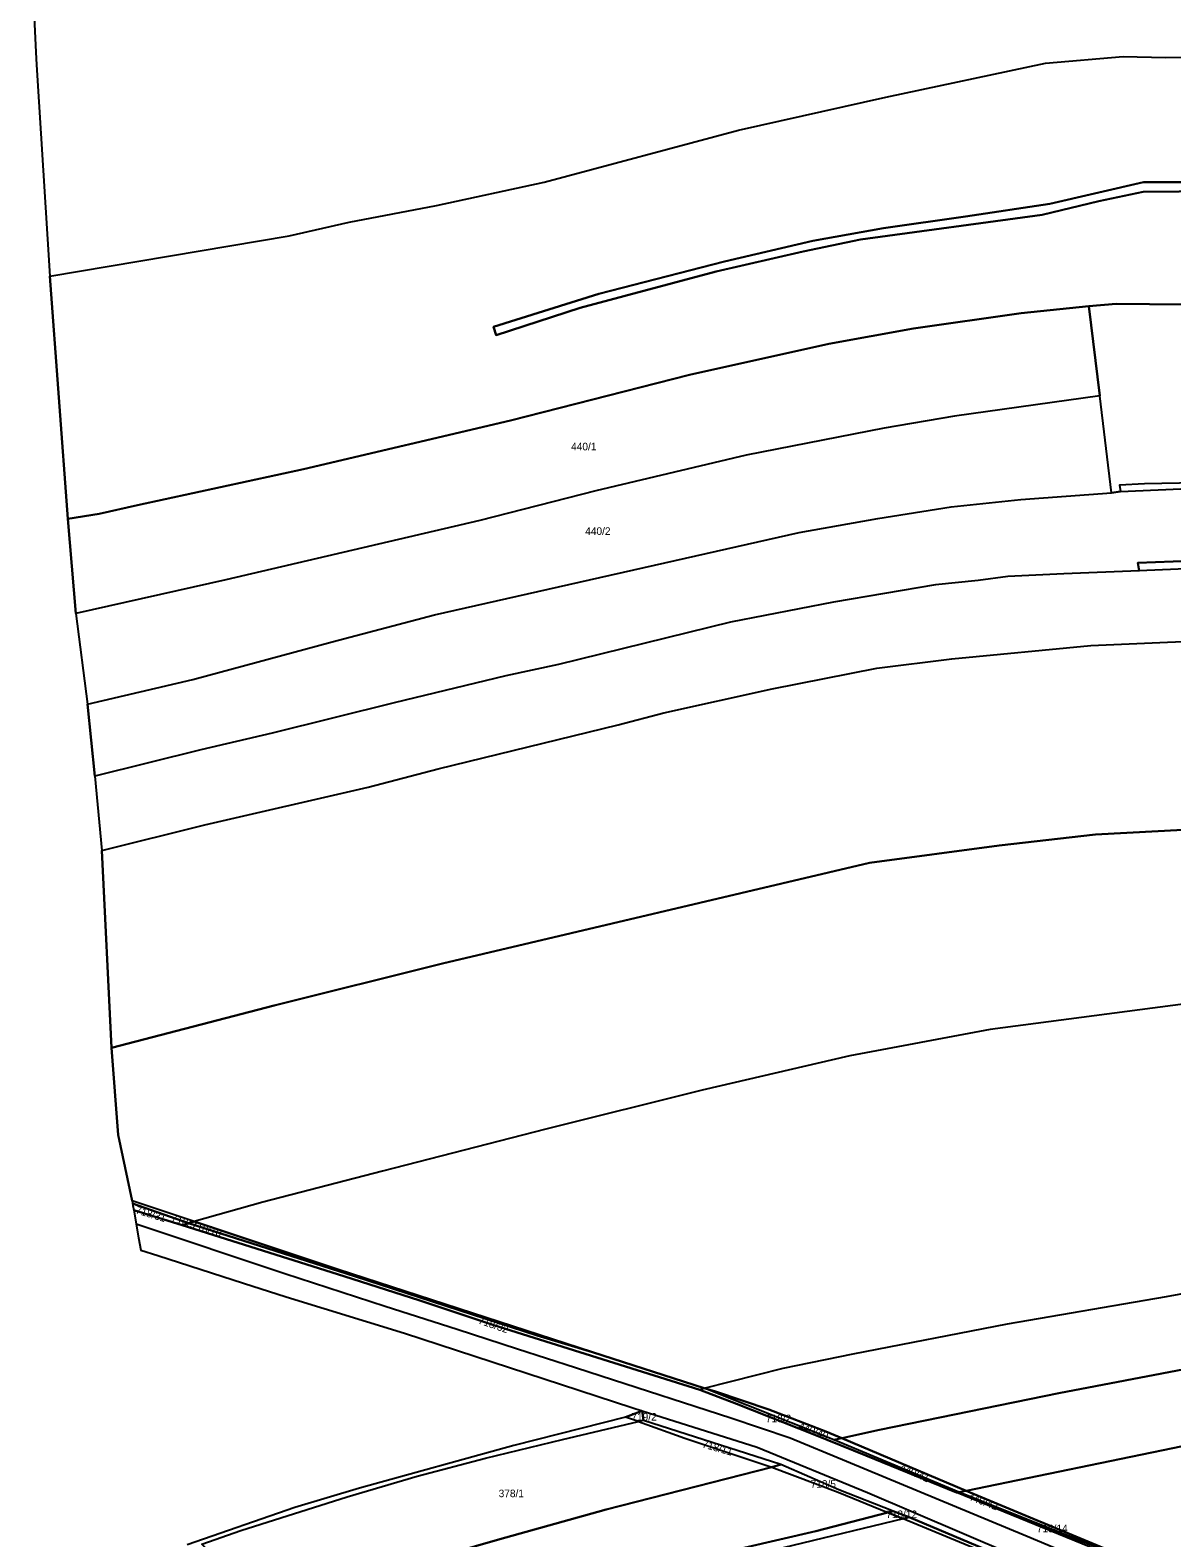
# Model space of a CAD drawing. Extents: x -629983 to -626385, y -1072828 to -1067897.
# Drawn here: x -629139 to -628686, y -1070643 to -1070045 of the extents above; entities that cross this region are included whole.
import ezdxf

# ---------------------------------------------------------------- set-up
doc = ezdxf.new("R2010")
doc.units = 0
for name, color, linetype in [('Parcela nároku', 7, 'Continuous'), ('Parcelní číslo', 7, 'Continuous'), ('Plocha PÚ', 7, 'Continuous'), ('Převzatý obvod_Ostrov', 7, 'Continuous'), ('Silnice ŘSD', 7, 'Continuous')]:
    doc.layers.add(name, color=color, linetype=linetype)

msp = doc.modelspace()

# ---------------------------------------------------------------- linework, layer by layer
at = {"layer": 'Parcela nároku'}
for points in [[(-629138.98, -1070006.71), (-629136.71, -1070053.9), (-629136.46, -1070058.86), (-629131.14, -1070142.73), (-629036.24, -1070126.79), (-629012.37, -1070121.35), (-628977.7, -1070114.76), (-628934.95, -1070105.43), (-628857.92, -1070084.77), (-628799.44, -1070071.72), (-628736.05, -1070058.27), (-628705.21, -1070055.58), (-628688.39, -1070055.9), (-628674.25, -1070055.65)], [(-628589.02, -1070154.96), (-628707.96, -1070153.76), (-628718.85, -1070154.67), (-628745.75, -1070157.44), (-628788.46, -1070163.52), (-628822.1, -1070169.63), (-628877.27, -1070181.92), (-628948.31, -1070200.02), (-629030.46, -1070219.36), (-629096.32, -1070233.61), (-629111.58, -1070237.07), (-629124.07, -1070239.08), (-629131.14, -1070142.73), (-629036.24, -1070126.79), (-629012.37, -1070121.35), (-628977.7, -1070114.76), (-628934.95, -1070105.43), (-628857.92, -1070084.77), (-628799.44, -1070071.72), (-628736.05, -1070058.27), (-628705.21, -1070055.58), (-628688.39, -1070055.9), (-628674.25, -1070055.65)], [(-628669.73, -1070105.5), (-628697.14, -1070105.5), (-628734.33, -1070114.1), (-628767.83, -1070119.02), (-628800.39, -1070123.65), (-628828.45, -1070128.69), (-628863.44, -1070136.88), (-628913.37, -1070149.74), (-628955.12, -1070162.9), (-628954.06, -1070166.1), (-628920.66, -1070155.36), (-628866.72, -1070140.86), (-628832.18, -1070132.93), (-628809.51, -1070128.17), (-628737.4, -1070118.38), (-628714.89, -1070112.98), (-628697.25, -1070109.21), (-628654.47, -1070108.86)], [(-628654.47, -1070108.86), (-628697.25, -1070109.21), (-628714.89, -1070112.98), (-628737.4, -1070118.38), (-628809.51, -1070128.17), (-628832.18, -1070132.93), (-628866.72, -1070140.86), (-628920.66, -1070155.36), (-628954.06, -1070166.1), (-628955.12, -1070162.9), (-628913.37, -1070149.74), (-628863.44, -1070136.88), (-628828.45, -1070128.69), (-628800.39, -1070123.65), (-628767.83, -1070119.02), (-628734.33, -1070114.1), (-628697.14, -1070105.5), (-628669.73, -1070105.5)], [(-628664.36, -1070255.18), (-628699.47, -1070256.47), (-628698.91, -1070259.7), (-628728.72, -1070260.8), (-628750.99, -1070261.89), (-628762.73, -1070263.47), (-628779.7, -1070265.23), (-628820.22, -1070272.05), (-628861.1, -1070280.08), (-628929.35, -1070296.86), (-628950.24, -1070301.32), (-628994.51, -1070312), (-629042.99, -1070324.08), (-629071.19, -1070330.68), (-629113.37, -1070341.21), (-629116.23, -1070312.6), (-629074.41, -1070302.73), (-629019.1, -1070287.84), (-628978.54, -1070277.09), (-628833.8, -1070244.48), (-628802.65, -1070238.87), (-628773.5, -1070234.3), (-628745.87, -1070231.39), (-628709.82, -1070228.71), (-628706.32, -1070228.2), (-628676.43, -1070226.93)], [(-628664.77, -1070258.22), (-628698.91, -1070259.7), (-628728.72, -1070260.8), (-628750.99, -1070261.89), (-628762.73, -1070263.47), (-628779.7, -1070265.23), (-628820.22, -1070272.05), (-628861.1, -1070280.08), (-628929.35, -1070296.86), (-628950.24, -1070301.32), (-628994.51, -1070312), (-629042.99, -1070324.08), (-629071.19, -1070330.68), (-629113.37, -1070341.21), (-629110.57, -1070370.67), (-629069.6, -1070360.43), (-629004.79, -1070345.52), (-628977.05, -1070338.23), (-628905.6, -1070320.75), (-628887.54, -1070316.04), (-628844.47, -1070306.46), (-628802.99, -1070298.36), (-628773.19, -1070294.62), (-628718.01, -1070289.28), (-628654.01, -1070286.5)], [(-628668.96, -1070361.81), (-628716.27, -1070364.26), (-628754.38, -1070368.64), (-628805.91, -1070375.5), (-628975.41, -1070415.52), (-629042.1, -1070432.17), (-629106.64, -1070448.89), (-629110.57, -1070370.67), (-629069.6, -1070360.43), (-629004.79, -1070345.52), (-628977.05, -1070338.23), (-628905.6, -1070320.75), (-628887.54, -1070316.04), (-628844.47, -1070306.46), (-628802.99, -1070298.36), (-628773.19, -1070294.62), (-628718.01, -1070289.28), (-628654.01, -1070286.5)], [(-628644.27, -1070426.67), (-628758.04, -1070441.74), (-628813.67, -1070452.18), (-628872.36, -1070465.79), (-628934.28, -1070481.24), (-628999.21, -1070497.87), (-629046.61, -1070510.16), (-629073.85, -1070517.9), (-629098.5, -1070509.68), (-629104.05, -1070483.52), (-629106.64, -1070448.89), (-629042.1, -1070432.17), (-628975.41, -1070415.52), (-628805.91, -1070375.5), (-628754.38, -1070368.64), (-628716.27, -1070364.26), (-628668.96, -1070361.81)], [(-628644.27, -1070426.67), (-628758.04, -1070441.74), (-628813.67, -1070452.18), (-628872.36, -1070465.79), (-628934.28, -1070481.24), (-628999.21, -1070497.87), (-629046.61, -1070510.16), (-629073.85, -1070517.9), (-629016.78, -1070536.93), (-628915.84, -1070569.67), (-628871.53, -1070584.05), (-628840.12, -1070576.07), (-628812.36, -1070570.34), (-628751.15, -1070558.46), (-628688.02, -1070547.57), (-628656.37, -1070541.84)], [(-628712.09, -1070649.57), (-628771.43, -1070625.39), (-628807.35, -1070610.7), (-628827.66, -1070602.5), (-628858.62, -1070590.22), (-628873.19, -1070584.64), (-628955.04, -1070559.06), (-628984.35, -1070549.18), (-629014.55, -1070539.6), (-629078.71, -1070519.31), (-629097.86, -1070513.38), (-629095.94, -1070524.41), (-629095.1, -1070529.21), (-629088.3, -1070531.4), (-629054.34, -1070542.32), (-629037.32, -1070547.8), (-628990.38, -1070562.19), (-628900.2, -1070591.71), (-628896.07, -1070593.06), (-628850.5, -1070607.36), (-628806.74, -1070625.37), (-628693.42, -1070673.79)], [(-628663.6, -1070573.19), (-628730.79, -1070586), (-628801.88, -1070600.56), (-628816.86, -1070603.82), (-628823.26, -1070601.21), (-628845.85, -1070592.51), (-628867.03, -1070585.32), (-628871.53, -1070584.05), (-628840.12, -1070576.07), (-628812.36, -1070570.34), (-628751.15, -1070558.46), (-628688.02, -1070547.57), (-628656.37, -1070541.84)], [(-628681.65, -1070607.07), (-628767.59, -1070624.69), (-628816.86, -1070603.82), (-628801.88, -1070600.56), (-628730.79, -1070586), (-628663.6, -1070573.19)], [(-628739.08, -1070656.78), (-628790.14, -1070635.22), (-628796.52, -1070632.78), (-628818.03, -1070624.38), (-628841.13, -1070614.34), (-628895.59, -1070596.79), (-628896.07, -1070593.06), (-628850.5, -1070607.36), (-628806.74, -1070625.37), (-628693.42, -1070673.79)], [(-629070.87, -1070645.91), (-629055.42, -1070640.49), (-629013.24, -1070627.11), (-628985.46, -1070618.93), (-628958.27, -1070611.77), (-628927.76, -1070604.32), (-628897.63, -1070597.26), (-628902.71, -1070595.48), (-628947.1, -1070606.82), (-629008.29, -1070623.66), (-629033.9, -1070631.38), (-629076.7, -1070646.21)], [(-628709.71, -1070648.87), (-628767.59, -1070624.69), (-628681.65, -1070607.07)]]:
    msp.add_lwpolyline(points, dxfattribs=at)
for points in [[(-628788.46, -1070163.52), (-628745.75, -1070157.44), (-628718.85, -1070154.67), (-628714.51, -1070190.29), (-628772.2, -1070198.28), (-628800.14, -1070203.05), (-628854.78, -1070213.76), (-628914.56, -1070227.96), (-628960.51, -1070239.73), (-629061.34, -1070263.21), (-629120.89, -1070276.56), (-629124.07, -1070239.08), (-629111.58, -1070237.07), (-629096.32, -1070233.61), (-629030.46, -1070219.36), (-628948.31, -1070200.02), (-628877.27, -1070181.92), (-628822.1, -1070169.63)], [(-628379.11, -1070173.77), (-628250.78, -1070202.28), (-628259.79, -1070238.1), (-628264.77, -1070261.35), (-628359.24, -1070238.39), (-628390.8, -1070232.96), (-628442.26, -1070228.67), (-628466.38, -1070227.31), (-628536.07, -1070225.95), (-628573.86, -1070225.34), (-628641.41, -1070224.05), (-628696.79, -1070225.17), (-628706.68, -1070225.65), (-628706.32, -1070228.2), (-628709.82, -1070228.71), (-628714.51, -1070190.29), (-628718.85, -1070154.67), (-628707.96, -1070153.76), (-628589.02, -1070154.96), (-628516.64, -1070158.65), (-628468.03, -1070161.59), (-628421.82, -1070167.01)], [(-629061.34, -1070263.21), (-629120.89, -1070276.56), (-629116.23, -1070312.6), (-629074.41, -1070302.73), (-629019.1, -1070287.84), (-628978.54, -1070277.09), (-628833.8, -1070244.48), (-628802.65, -1070238.87), (-628773.5, -1070234.3), (-628745.87, -1070231.39), (-628709.82, -1070228.71), (-628714.51, -1070190.29), (-628772.2, -1070198.28), (-628800.14, -1070203.05), (-628854.78, -1070213.76), (-628914.56, -1070227.96), (-628960.51, -1070239.73)], [(-628573.86, -1070225.34), (-628641.41, -1070224.05), (-628696.79, -1070225.17), (-628706.68, -1070225.65), (-628706.32, -1070228.2), (-628676.43, -1070226.93), (-628641.43, -1070225.97), (-628548.86, -1070228.15), (-628496.37, -1070229.17), (-628472.75, -1070229.44), (-628405.88, -1070233.81), (-628389.6, -1070235.8), (-628356.96, -1070242.24), (-628265.56, -1070264.98), (-628264.77, -1070261.35), (-628359.24, -1070238.39), (-628390.8, -1070232.96), (-628442.26, -1070228.67), (-628466.38, -1070227.31), (-628536.07, -1070225.95)], [(-628340.63, -1070272.61), (-628271.49, -1070288.24), (-628203.49, -1070303.75), (-628203.99, -1070306.2), (-628214, -1070304.38), (-628317.59, -1070280.52), (-628365.18, -1070270.35), (-628403.66, -1070262.78), (-628433.52, -1070259), (-628452.82, -1070257.33), (-628510.86, -1070255.71), (-628594.38, -1070256.49), (-628664.77, -1070258.22), (-628698.91, -1070259.7), (-628699.47, -1070256.47), (-628664.36, -1070255.18), (-628553.7, -1070253.06), (-628483.88, -1070253.57), (-628441.52, -1070255.31), (-628402.14, -1070259.92)], [(-629098.5, -1070509.68), (-629098.32, -1070510.72), (-629076.2, -1070518.58), (-629073.85, -1070517.9)], [(-629098.18, -1070511.52), (-629097.86, -1070513.38), (-629078.71, -1070519.31), (-629076.2, -1070518.58), (-629098.32, -1070510.72)], [(-628871.53, -1070584.05), (-628915.84, -1070569.67), (-628937.72, -1070563.05), (-629010.25, -1070539.5), (-629076.2, -1070518.58), (-629078.71, -1070519.31), (-629014.55, -1070539.6), (-628984.35, -1070549.18), (-628955.04, -1070559.06), (-628873.19, -1070584.64)], [(-628915.84, -1070569.67), (-629016.78, -1070536.93), (-629073.85, -1070517.9), (-629076.2, -1070518.58), (-629010.25, -1070539.5), (-628937.72, -1070563.05)], [(-628820.11, -1070604.53), (-628871.53, -1070584.05), (-628873.19, -1070584.64), (-628858.62, -1070590.22), (-628827.66, -1070602.5), (-628807.35, -1070610.7), (-628771.43, -1070625.39), (-628770.47, -1070625.28)], [(-628871.53, -1070584.05), (-628867.03, -1070585.32), (-628845.85, -1070592.51), (-628823.26, -1070601.21), (-628816.86, -1070603.82), (-628820.11, -1070604.53)], [(-628902.71, -1070595.48), (-628896.07, -1070593.06), (-628895.59, -1070596.79), (-628897.63, -1070597.26)], [(-629013.24, -1070627.11), (-628985.46, -1070618.93), (-628958.27, -1070611.77), (-628927.76, -1070604.32), (-628897.63, -1070597.26), (-628879.21, -1070603.9), (-628844.64, -1070615.42), (-628910.36, -1070632.1), (-628953.49, -1070644.17), (-629046.78, -1070671.08), (-629070.87, -1070645.91), (-629055.42, -1070640.49)], [(-628895.59, -1070596.79), (-628897.63, -1070597.26), (-628879.21, -1070603.9), (-628844.64, -1070615.42), (-628841.13, -1070614.34)], [(-628816.86, -1070603.82), (-628767.59, -1070624.69), (-628770.47, -1070625.28), (-628820.11, -1070604.53)], [(-628910.36, -1070632.1), (-628844.64, -1070615.42), (-628818.36, -1070625.27), (-628798.59, -1070633.32), (-628827.25, -1070640.79), (-628914.69, -1070661.01), (-628970.38, -1070676.11), (-629025.16, -1070694.08), (-629046.78, -1070671.08), (-628953.49, -1070644.17)], [(-628796.52, -1070632.78), (-628818.03, -1070624.38), (-628841.13, -1070614.34), (-628844.64, -1070615.42), (-628818.36, -1070625.27), (-628798.59, -1070633.32)], [(-628771.43, -1070625.39), (-628770.47, -1070625.28), (-628710.73, -1070649.1), (-628712.09, -1070649.57)], [(-628770.47, -1070625.28), (-628767.59, -1070624.69), (-628709.71, -1070648.87), (-628710.73, -1070649.1)], [(-628798.59, -1070633.32), (-628792.54, -1070635.8), (-628923.84, -1070667.59), (-628972.69, -1070680.79), (-629022.54, -1070696.84), (-629025.16, -1070694.08), (-628970.38, -1070676.11), (-628914.69, -1070661.01), (-628827.25, -1070640.79)], [(-628796.52, -1070632.78), (-628790.14, -1070635.22), (-628792.54, -1070635.8), (-628798.59, -1070633.32)], [(-628792.54, -1070635.8), (-628790.14, -1070635.22), (-628739.08, -1070656.78), (-628740.78, -1070657.25), (-628741.75, -1070656.84)], [(-628972.69, -1070680.79), (-629022.54, -1070696.84), (-629008.29, -1070713.3), (-628996.19, -1070728.53), (-628948.21, -1070713.55), (-628918.79, -1070705.29), (-628875.5, -1070693.93), (-628831.39, -1070682.06), (-628740.78, -1070657.25), (-628741.75, -1070656.84), (-628792.54, -1070635.8), (-628923.84, -1070667.59)]]:
    msp.add_lwpolyline(points, close=True, dxfattribs=at)
at = {"layer": 'Plocha PÚ'}
msp.add_lwpolyline([(-629138.98, -1070006.71), (-629136.71, -1070053.9), (-629136.46, -1070058.86), (-629131.14, -1070142.73), (-629124.07, -1070239.08), (-629120.89, -1070276.56), (-629116.23, -1070312.6), (-629113.37, -1070341.21), (-629110.57, -1070370.67), (-629106.64, -1070448.89), (-629104.05, -1070483.52), (-629098.5, -1070509.68), (-629098.32, -1070510.72), (-629098.18, -1070511.52), (-629097.86, -1070513.38), (-629095.94, -1070524.41), (-629095.1, -1070529.21), (-629088.3, -1070531.4), (-629054.34, -1070542.32), (-629037.32, -1070547.8), (-628990.38, -1070562.19), (-628900.2, -1070591.71), (-628896.07, -1070593.06), (-628902.71, -1070595.48), (-628947.1, -1070606.82), (-629008.29, -1070623.66), (-629033.9, -1070631.38), (-629076.7, -1070646.21)], dxfattribs=at)
at = {"layer": 'Převzatý obvod_Ostrov'}
msp.add_lwpolyline([(-629138.98, -1070006.71), (-629136.71, -1070053.9), (-629136.46, -1070058.86), (-629131.14, -1070142.73), (-629124.07, -1070239.08), (-629120.89, -1070276.56), (-629116.23, -1070312.6), (-629113.37, -1070341.21), (-629110.57, -1070370.67), (-629106.64, -1070448.89), (-629104.05, -1070483.52), (-629098.5, -1070509.68), (-629098.32, -1070510.72), (-629098.18, -1070511.52), (-629097.86, -1070513.38), (-629095.94, -1070524.41), (-629095.1, -1070529.21), (-629088.3, -1070531.4), (-629054.34, -1070542.32), (-629037.32, -1070547.8), (-628990.38, -1070562.19), (-628900.2, -1070591.71), (-628896.07, -1070593.06), (-628902.71, -1070595.48), (-628947.1, -1070606.82), (-629008.29, -1070623.66), (-629033.9, -1070631.38), (-629076.7, -1070646.21)], dxfattribs=at)
at = {"layer": 'Silnice ŘSD'}
for p, q in [((-629037.94, -1070538.62), (-629096.9, -1070518.9)), ((-628998.06, -1070551.54), (-629037.94, -1070538.62)), ((-628969.5, -1070560.79), (-628998.06, -1070551.54)), ((-628945.53, -1070568.55), (-628969.5, -1070560.79)), ((-628922.53, -1070576), (-628945.53, -1070568.55)), ((-628912.37, -1070579.29), (-628922.53, -1070576)), ((-628860.92, -1070595.94), (-628912.37, -1070579.29)), ((-628837.35, -1070603.88), (-628860.92, -1070595.94)), ((-628815.01, -1070613.16), (-628837.35, -1070603.88)), ((-628743.38, -1070642.92), (-628815.01, -1070613.16)), ((-628691.15, -1070664.62), (-628743.38, -1070642.92))]:
    msp.add_line(p, q, dxfattribs=at)

# ---------------------------------------------------------------- texts
at = {"layer": 'Parcelní číslo'}
for s, p in [('440/1', (-628924.31, -1070211.84)), ('440/2', (-628918.71, -1070245.41)), ('719/2', (-628900.39, -1070596.89)), ('718/2', (-628847.03, -1070597.51)), ('718/5', (-628829.26, -1070623.53)), ('378/1', (-628953.06, -1070627.27)), ('718/12', (-628799.3, -1070635.56)), ('718/14', (-628739.52, -1070641.18))]:
    msp.add_text(s, height=3, dxfattribs=at).set_placement(p)
for s, rotation, p in [('718/31', 343.06209, (-629097.4, -1070514.56)), ('718/9', 341.4582, (-629083.24, -1070517.65)), ('718/10', 342.79092, (-629075.24, -1070520.4)), ('718/32', 340.96293, (-628961.41, -1070558.27)), ('440/40', 338.82624, (-628834.39, -1070600.11)), ('718/11', 343.94238, (-628872.53, -1070607.45)), ('440/41', 335.75832, (-628794.15, -1070616.41)), ('440/42', 338.86278, (-628767.06, -1070628.12))]:
    msp.add_text(s, height=3, rotation=rotation, dxfattribs=at).set_placement(p)

doc.saveas('drawing.dxf')
